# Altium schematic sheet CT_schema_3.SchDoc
size 293 x 258 mm
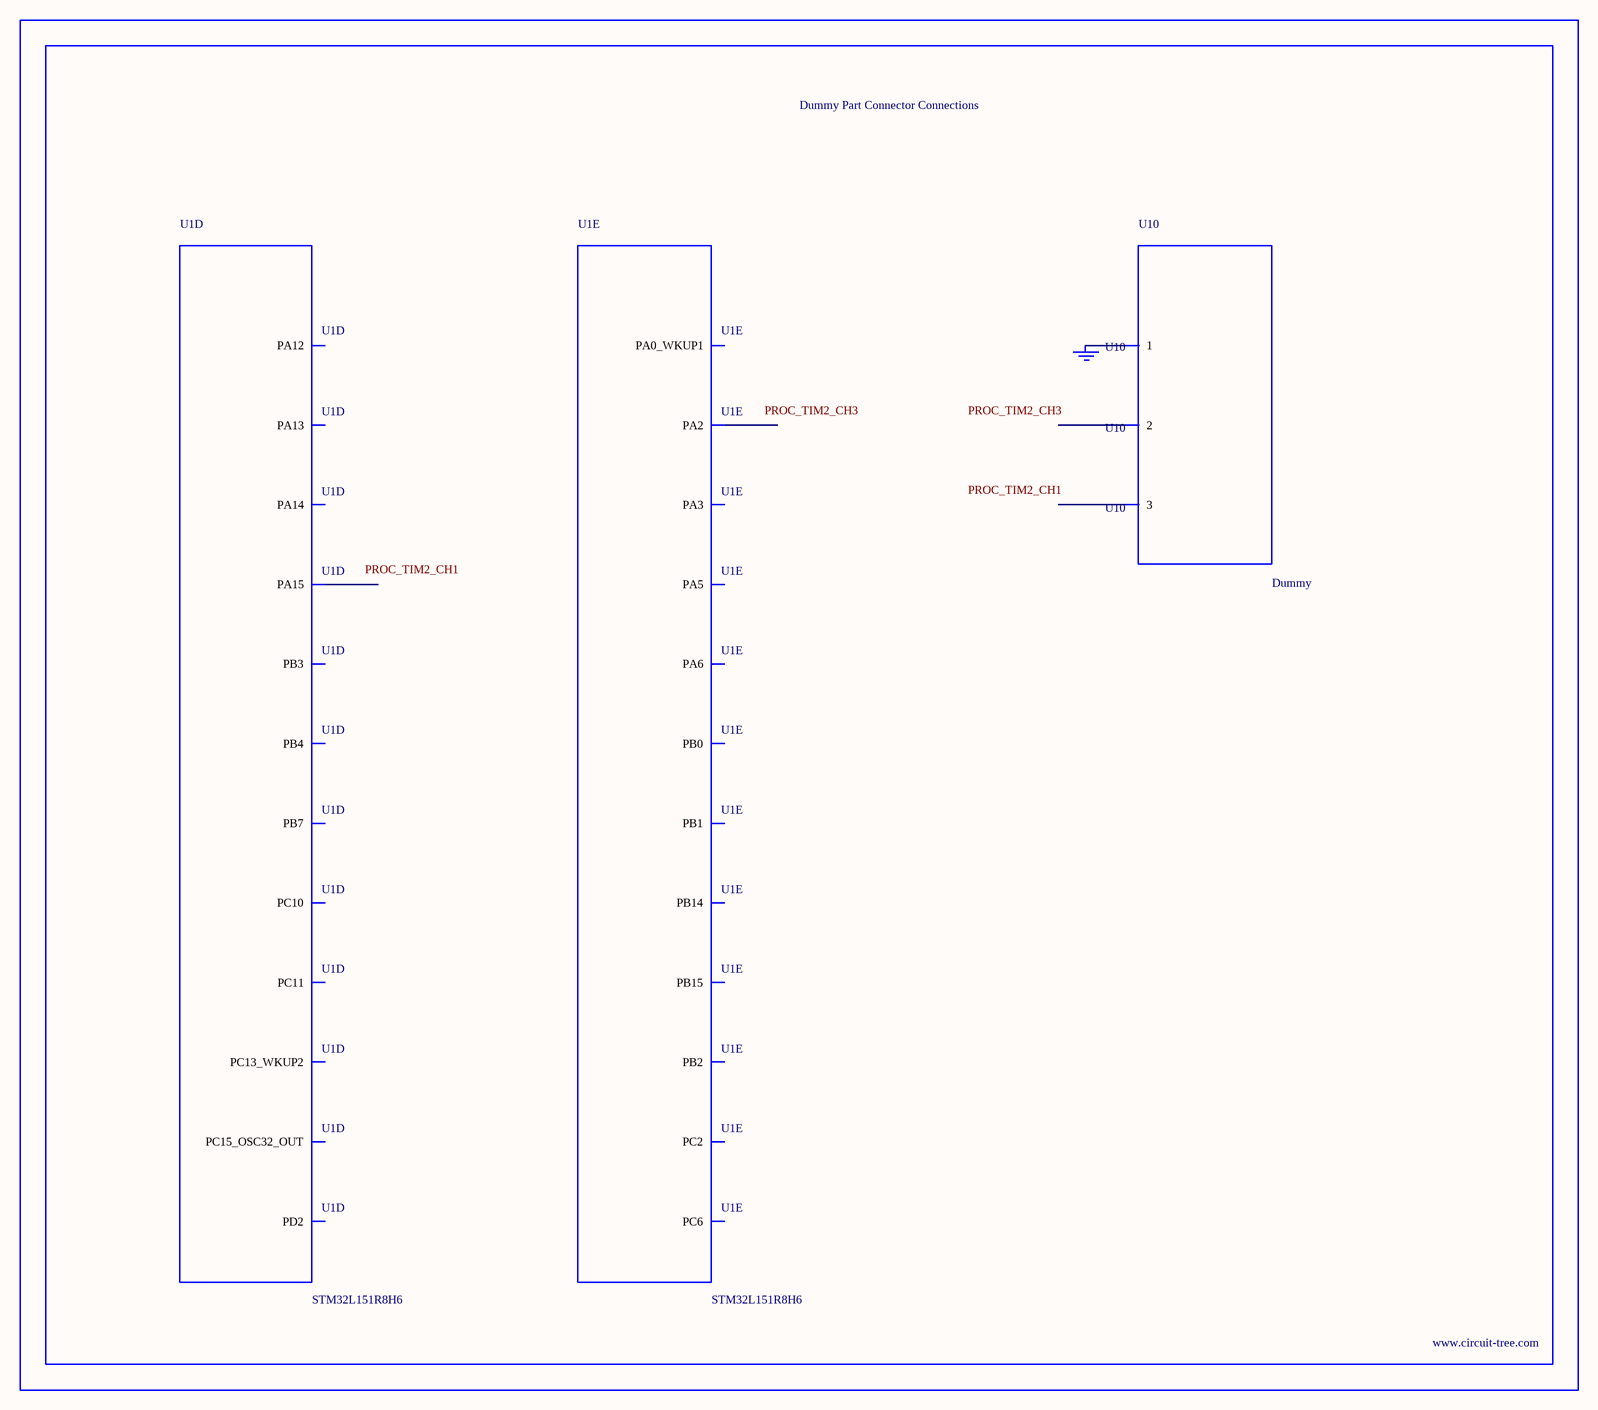
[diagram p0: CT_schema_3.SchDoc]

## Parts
BORDER2  (no value)
GND_INSTANCE_2_0  (no value)
U1  STM32L151R8H6  [TFBGA64]  (parts D,E of 5)
U10  Dummy  [DUMMY_PACKAGE_90]

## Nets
NetGND_INSTANCE_2_0_0: GND_INSTANCE_2_0.0(GND) U10.1

Not connected (* = marked no-connect by the designer): U1 A2(PC13_WKUP2) A4(PB4) A5(PB3) A6(PA15) A7(PA14) A8(PA13) B1(PC15_OSC32_OUT) B5(PD2) B6(PC11) B7(PC10) B8(PA12) C3(PB7) F2(PC2) F3(PA2) F4(PA5) F5(PB0) F6(PC6) F7(PB15) F8(PB14) G2(PA0_WKUP1) G3(PA3) G4(PA6) G5(PB1) G6(PB2); U10 2 3

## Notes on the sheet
- Labels drawn without touching a wire or pin: PROC_TIM2_CH1, PROC_TIM2_CH3

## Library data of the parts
BORDER2 = BORDER_PAGE2
GND_INSTANCE_2_0 = GND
